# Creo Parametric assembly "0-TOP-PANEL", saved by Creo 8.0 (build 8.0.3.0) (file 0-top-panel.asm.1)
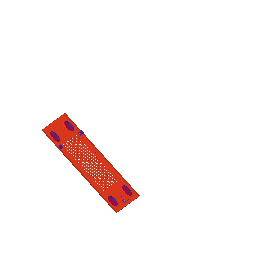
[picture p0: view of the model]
Units: millimeter Newton Second (mmNs); MM, TONNE, SECS

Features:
  1. datum plane "ADTM1"
  2. datum plane "ADTM2"
  3. datum plane "ADTM3"
  4. coordinate system
  5. component "1_TOP-COVER"
  6. component
  7. component
  8. component
  9. component
  10. component
  11. component
  12. component
  13. component
  14. component "0_TOP-COVER-BRACK"
  15. component "2_GROUND-SCREW-COVER"
  16. component "2_GROUND-SCREW-COVER"
  17. component "2_GROUND-SCREW-COVER"
  18. component "2_GROUND-SCREW-COVER"
  19. component "2_GROUND-SCREW-COVER"
  20. component "1_HOOK"
  21. component "1_HOOK"
  22. component "1_HOOK"
  23. component "4_GROUNDING_MARK"
  24. component "3_WASHER"
  25. component "3_WASHER"
  26. component "3_WASHER"
  27. component "3_FIXING-NUT"
  28. component "3_FIXING-NUT"
  29. component "3_FIXING-NUT"

Other named items: ACS0, VIS0001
